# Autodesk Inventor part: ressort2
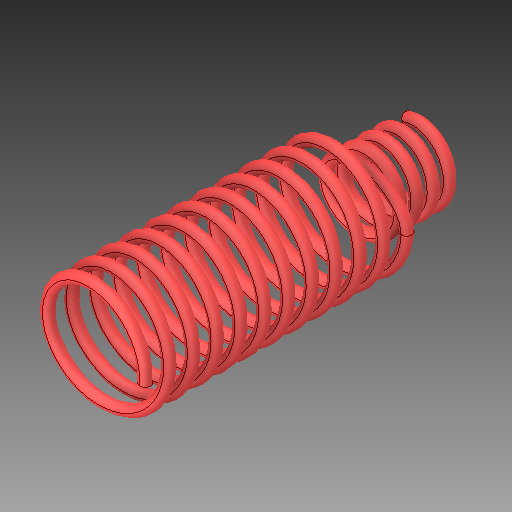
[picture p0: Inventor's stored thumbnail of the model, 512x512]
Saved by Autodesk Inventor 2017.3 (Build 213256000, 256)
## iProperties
Created: 2007-11
Part Number: ressort2
Material: Générique
Document SubType Name: Modeling
Designer: ficho
Density: 1 g/cm^3
Appearance: Par défaut
Author: ficho
Sending System: SolidWorks 2009
Last Author: christophe
Last Saved: 2011-02-10
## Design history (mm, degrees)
feature "Lissage1"
node "Solide1"
